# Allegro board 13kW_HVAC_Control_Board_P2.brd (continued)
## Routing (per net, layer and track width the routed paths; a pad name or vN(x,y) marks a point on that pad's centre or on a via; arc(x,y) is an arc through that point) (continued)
NETD4_1: length 16.3
  BOTTOM w0.508: U9.6 69.72,33.66 71.64,31.73 71.64,27.06 71.13,26.54 69.9,26.54 69.28,25.93 69.28,24.91 D4.1 D6.2 69.43,22.57 68.56,21.7 T1.1
NETDACA_1: length 2.7
  TOP w0.305: R140.2 24.92,14.1 DACA.1
NETDACB_1: length 2.8
  TOP w0.305: DACB.1 25.27,15.62 R142.2
NETIC1_1: length 7.4
  TOP w0.254: IC1.1 58.45,34.31 57.93,33.78 57.93,30.34 R33.2
NETJ4_5: length 7.2
  BOTTOM w0.254: R20.1 51.44,9.6 53.98,7.06 53.98,5.31 J4.5
NETJ4_9: length 9
  BOTTOM w0.254: J4.11 J4.9 48.9,5.31 48.9,7.62 47.76,8.75 R24.1
NETJ4_13: length 6.1
  BOTTOM w0.254: J4.13 46.35,5.31 R25.2
NETJ4_14: length 3.1
  BOTTOM w0.254: R23.2 J4.14
NETQ1_1: length 2.9
  BOTTOM w0.305: Q1.1 2.86,10.35 R18.2 R15.1
NETQ2_1: length 1.4
  TOP w0.508: R34.2 68.58,16.13 Q2.1
NETR7_1: length 6.5
  TOP w0.203: v2(50.33,20.32) 48.64,20.32 47.51,21.46 U1.64
  BOTTOM w0.254: R7.1 v2(50.33,20.32)
NETR8_1: length 4.9
  TOP w0.203: v2(47.62,14.28) 47.89,14.55 47.89,17.08 47.66,17.31 47.46,17.31 47.32,17.45 U1.56
  BOTTOM w0.254: R8.1 v2(47.62,14.28)
NETR12_2: length 3.8
  TOP w0.381: U2.19 13.64,7.95 13.72,7.87 R12.2 R13.2
NETR14_2: length 3.2
  TOP w0.381: R14.2 4.2,5.71 5.13,6.64 U2.8
NETR36_1: length 17.8
  TOP w0.203: U1.54 45.65,16.45 45.49,16.3 45.49,14.17 45.28,13.96 45.28,12.37 v1(44.65,11.74)
  GND02 w0.203: v1(42.71,5.66) 42.39,5.98 42.39,10.85 43.28,11.74 v1(44.65,11.74)
  BOTTOM w0.203: R36.1 39.73,4.55 40.84,5.66 v1(42.71,5.66)
NETR37_1: length 18.3
  TOP w0.203: U1.55 47.35,16.96 47.54,16.77 47.54,14.84 47.05,14.35 46.61,14.35 45.65,13.39 45.65,12 45.45,11.79 v1(45.45,11.71)
  GND02 w0.203: v1(45.45,11.71) 44.89,11.15 43.27,11.15 42.72,10.6 42.72,6.42 43.28,5.86 43.28,5.21 v1(42.68,4.61)
  BOTTOM w0.203: R37.1 v1(42.68,4.61)
NETR39_1: length 2.2
  TOP w0.508: R161.1 22.86,34.08 R39.1
NETR47_1: length 2.3
  TOP w0.508: R48.2 R47.1
NETR54_1: length 5
  TOP w0.508: U4.2 19.68,18.8 19.56,18.92 18.67,18.92 18.41,18.67 U4.1 R54.1
NETR69_1: length 2.3
  TOP w0.508: R69.1 R70.2
NETR71_1: length 2.3
  TOP w0.508: R72.2 R71.1
NETR75_2: length 2.6
  TOP w0.508: R75.2 69.66,28.42 70.2,28.89 v2(70.23,29.21)
  BOTTOM w0.508: U9.8 v2(70.23,29.21)
NETR78_1: length 2.3
  TOP w0.508: R79.2 R78.1
NETR83_1: length 2.3
  TOP w0.508: R83.1 R84.2
NETR89_1: length 2.3
  TOP w0.508: R90.2 R89.1
NETR91_1: length 2.3
  TOP w0.508: R92.2 R91.1
NETR94_1: length 12
  TOP w0.254: R94.1 57.78,21.08 57.53,20.83 57.53,13.97 58.8,12.7 59.56,12.7 60.2,12.06 U10.8
NETR95_2: length 10.1
  TOP w0.254: R95.2 56.77,21.34 57.02,21.08 57.02,13.84 56.52,13.34 U10.6
NETR97_1: length 9.4
  TOP w0.254: U10.10 60.2,14.61 59.56,15.24 58.93,15.24 58.04,16.13 58.04,20.32 58.42,20.7 58.42,21.47 R97.1
NETR100_2: length 8.6
  TOP w0.254: R100.2 54.74,21.34 54.48,21.08 53.94,21.08 52.96,20.1 52.96,18.8 53.42,18.34 53.42,16.56 54.1,15.88 U10.4
NETR102_1: length 7.2
  TOP w0.254: R102.1 59.82,20.83 59.31,20.32 58.8,20.32 58.55,20.07 58.55,18.16 58.93,17.78 59.56,17.78 60.2,17.14 U10.12
NETR104_2: length 6.5
  TOP w0.254: R104.2 55.75,21.08 55.24,20.57 53.98,20.57 53.47,20.07 53.47,19.05 54.1,18.41 U10.2
NETR114_1: length 3.9
  TOP w0.254: U1.35 37.23,12.51 35.56,10.84 R114.1
NETR116_1: length 3.5
  TOP w0.254: R116.1 28.57,22.23 29.06,22.71 30.04,22.71 30.3,22.46 U1.10
NETR117_1: length 3.9
  TOP w0.254: U1.6 30.03,24.46 29.21,25.27 29.21,25.9 R117.1
NETR118_1: length 3.5
  TOP w0.254: U1.38 38.73,10.66 R118.1
NETR120_1: length 2.9
  TOP w0.254: U1.8 30.27,23.46 29.09,24.63 R120.1
NETR122_1: length 3.3
  TOP w0.254: U1.39 39.24,10.16 R122.1
NETR124_1: length 2.6
  TOP w0.254: R124.1 29.27,18.28 29.59,17.96 U1.19
NETR127_1: length 6.9
  TOP w0.254: R127.1 30.49,11.3 33.27,11.3 34.23,12.26 U1.29
NETR129_1: length 11.3
  TOP w0.254: v1(27.39,16.38) 28.88,16.38 29.45,16.96 U1.21 ; v1(27.25,13.14) 27.25,13.11 26.97,12.83 24.26,12.83 23.89,12.46 R129.1
  GND02 w0.254: v1(27.25,13.14) 27.25,16.24 v1(27.39,16.38)
NETR140_1: length 3.9
  TOP w0.254: R140.1 29.07,14.1 29.34,14.36 29.34,15.38 29.92,15.96 U1.23
NETR142_1: length 2.9
  TOP w0.254: R142.1 28.83,15.62 29.66,16.45 U1.22
NETR155_2: length 5
  TOP w0.254: U1.31 35.23,11.87 34.67,11.3 34.04,11.3 32.76,10.02 R155.2
NETR158_2: length 9.5
  TOP w0.254: R158.2 26.46,10.02 26.97,10.54 27.01,10.54 27.23,10.76 27.23,10.8 27.74,11.3 29.21,11.3 29.72,11.81 33.15,11.81 33.74,12.4 U1.28
NETT1_2: length 2.4
  BOTTOM w0.508: T1.2 T2.1
NETT1_3: length 2.4
  BOTTOM w0.508: T2.4 T1.3
NETU6_6: length 2.7
  BOTTOM w0.508: U6.7 15.88,23.24 16.13,22.99 16.89,22.99 17.14,23.24 17.14,23.87
P_-2.7V: length 23.3
  TOP w0.508: U11.4 42.55,43.18 v2(41.91,42.55)
  GND03 w0.508: v2(41.91,42.55) 41.15,43.31 36.45,43.31 34.82,41.68 26.67,41.68 J1.20
  BOTTOM w0.508: C111.1 C112.2 42.55,43.19 42.55,43.18 v2(41.91,42.55) 42.55,41.91 U12.4
PWM-1A: length 28.1
  TOP w0.254: R94.2 57.78,23.39 57.04,24.13 57.04,26.7 56.44,27.3 56.44,38.56 55.24,39.75 55.24,41.02 55.88,41.66 57.02,41.66 57.78,42.42 57.78,43.69 57.28,44.2 55.22,44.2 J2.2
PWM-1AA: length 36.8
  TOP w0.254: U1.79 43.24,29.79 v2(42.55,30.48) R1.2
  BOTTOM w0.254: v2(42.55,30.48) 44.32,28.7 47.06,28.7 47.94,27.81 53.21,27.81 54.61,26.42 54.61,23.16 52.78,21.33 52.78,16.44 55.24,13.97 57.28,13.97 59.18,12.06 R96.1
PWM-1B: length 26.5
  TOP w0.254: R95.1 56.77,23.41 56.29,23.89 56.29,26.44 55.23,27.5 55.23,36.56 55.88,37.21 55.88,38.35 55.5,38.73 53.21,38.73 52.83,39.12 52.83,41.53 53.09,41.78 54.74,41.78 55.9,42.95 J2.4
PWM-1BB: length 28.6
  TOP w0.254: U1.78 43.73,30.4 v2(43.81,30.48) R2.2
  BOTTOM w0.254: v2(43.81,30.48) 43.81,29.97 44.58,29.21 47.62,29.21 48.64,28.19 53.37,28.19 54.99,26.57 54.99,22.85 53.34,21.2 53.34,16.76 54.23,15.88 R98.1
PWM-2A: length 21.8
  TOP w0.254: R97.2 58.8,23.27 57.71,24.36 57.71,26.85 56.9,27.66 56.9,37.89 57.78,38.78 57.78,41.68 J2.6
PWM-2AA: length 30.7
  TOP w0.254: R3.2 v2(45.09,30.48) 44.24,29.63 U1.77
  BOTTOM w0.254: v2(45.09,30.48) 45.72,31.11 47.88,31.11 49.66,29.34 53.84,29.34 56.13,27.05 56.13,22.61 57.91,20.83 57.91,18.03 58.55,17.4 58.55,15.62 58.93,15.24 59.19,15.24 R99.1
PWM-2B: length 29.8
  TOP w0.254: R100.1 54.74,23.24 55.34,23.85 55.34,26.26 54.41,27.19 54.41,37.66 v2(53.98,38.1)
  BOTTOM w0.254: J2.8 62.87,41.68 62.87,39.88 62.23,39.24 61.34,39.24 60.58,38.48 57.4,38.48 56.39,37.47 54.61,37.47 v2(53.98,38.1)
PWM-2BB: length 25
  TOP w0.254: U1.76 44.73,29.34 44.99,29.59 45.47,29.59 v2(46.35,30.48) R4.2
  BOTTOM w0.254: v2(46.35,30.48) 47.88,30.48 49.4,28.96 53.69,28.96 55.75,26.89 55.75,22.35 57.02,21.08 57.02,18.92 56.52,18.41 R101.1
PWM-3A: length 19.3
  TOP w0.254: J2.5 59.05,38.78 57.33,37.05 57.33,28.02 58.36,26.99 58.36,24.57 59.82,23.11 R102.2
PWM-3AA: length 25.3
  TOP w0.254: v2(50.16,30.48) 48.4,28.71 R5.2 47.5,27.3 47.15,26.95 U1.75
  BOTTOM w0.254: v2(50.16,30.48) 50.8,29.84 53.88,29.84 56.52,27.21 56.52,22.86 58.42,20.95 58.42,18.29 58.93,17.78 59.19,17.78 R103.1
PWM-3B: length 23.1
  TOP w0.254: R104.1 55.75,26.39 54.79,27.35 54.79,37.65 v2(55.24,38.1)
  BOTTOM w0.254: v2(55.24,38.1) 56.12,38.1 57.14,39.12 60.3,39.12 J2.7
PWM-3BB: length 27.9
  TOP w0.254: R6.2 v2(41.27,31.11) 40.51,30.35 38.51,30.35 38.24,30.08 U1.89
  BOTTOM w0.254: R105.2 54.75,21.45 55.37,22.08 55.37,26.73 53.53,28.57 49.02,28.57 47.88,29.72 44.96,29.72 44.45,30.23 44.45,30.73 44.07,31.11 v2(41.27,31.11)
R_12V: length 18.4
  TOP w0.508: J3.1 70.87,18.29 70.87,19.73 71.88,20.75 71.88,33.53 71.1,34.31 IC1.4
R_GND: length 10.2
  TOP w0.508: R35.1 66.67,17.41 ; 66.67,17.41 66.61,17.35 66.61,16.06 Q2.2 66.61,15.04 66.61,15.03 66.61,13.06 67.12,12.55 70.21,12.55 J3.3 ; 66.67,17.41 67.31,17.41 C35.2
REF1.65: length 22.4
  TOP w0.508: C94.1 41.27,43.18 v2(40.64,42.55) 40.01,43.18 R107.2 ; C98.1 40.01,39.37 v2(40.64,40.01) 41.27,39.37 R139.2
  GND03 w0.508: v1(45.23,39.37) 41.27,39.37 v2(40.64,40.01) v2(40.64,42.55)
  BOTTOM w0.508: R147.2 40.01,41.91 v2(40.64,42.55) 41.27,41.91 C103.1 ; U12.6 45.74,40.64 45.23,40.13 v1(45.23,39.37) U12.7
RELAY: length 39.7
  TOP w0.254: U1.50 44.73,12.55 44.05,11.87 44.05,11.32 44.22,11.15 45.86,11.15 46.21,10.79 46.7,10.79 46.7,10.79 61.15,10.79 63.2,12.84 63.2,19.72 62.55,20.37 61.36,20.37 60.73,21 60.73,23.05 59.73,24.04 59.73,27.54 R33.1
RLY: length 3.9
  TOP w0.508: J3.2 68.97,13.86 Q2.3
SCIA_RX: length 2.1
  BOTTOM w0.254: J6.2 41.35,3.6 R37.2
SCIA_TX: length 2.6
  BOTTOM w0.254: R36.2 38.81,4.02 J6.1
SCL: length 7.5
  TOP w0.203: v2(50.16,14.61) U3.6 50.16,16.76 48.63,18.3 47.99,18.3 47.34,18.96 U1.59
  BOTTOM w0.254: R31.1 v2(50.16,14.61)
SDA: length 6.5
  TOP w0.203: v2(48.9,14.61) 48.9,17.44 48.36,17.97 47.81,17.97 47.33,18.45 U1.58
  BOTTOM w0.254: R30.1 v2(48.9,14.61)
TCK_P: length 13.7
  TOP w0.203: U1.60 47.35,19.45 48.17,18.63 48.87,18.63 49.35,18.15 49.8,18.15 v2(50.16,17.78)
  BOTTOM w0.203: R24.2 R22.1 48.76,11.44 48.26,11.94 48.26,15.88 v2(50.16,17.78)
TDI_P: length 24.4
  TOP w0.203: U1.63 47.47,20.95 48.74,19.68 50.77,19.68 51.44,19.02 v2(51.44,17.76)
  BOTTOM w0.203: v2(51.44,17.76) 51.44,15.37 52.07,14.73 52.07,10.22 52.63,9.66 R19.1 54.17,8.2 55.81,8.2 56.52,7.49 56.52,5.31 J4.3
TDO_P: length 21.3
  TOP w0.203: v2(50.67,18.51) 50.59,18.59 49.52,18.59 49.11,19 48.27,19 47.31,19.96 U1.61
  BOTTOM w0.203: R21.1 49.78,9.66 49.53,9.91 49.53,16 50.67,17.14 v2(50.67,18.51)
  BOTTOM w0.254: J4.7 51.44,5.31 51.44,7.75 50.16,9.02 R21.1
TEMP: length 25.1
  TOP w0.254: v2(21.59,22.23) 20.95,21.59 U4.3
  BOTTOM w0.254: v2(21.59,22.23) R56.2 20.32,23 C46.2 19.93,22.99 19.68,23.24 19.68,33.4 19.05,34.04 19.05,39.14 J1.13
TEMP1: length 19.5
  TOP w0.254: R117.2 26.48,26.67 v2(26.23,26.42) 25.1,26.42 23.8,25.12 23.19,25.12 22.94,24.87 22.94,17.04 20.63,14.74 C47.1 R54.2
  BOTTOM w0.254: v2(26.23,26.42) 26.21,26.42 26.2,26.43 D8.3
TMS_P: length 28.2
  TOP w0.203: U1.62 47.39,20.46 48.52,19.33 49.43,19.33 v2(49.71,19.05)
  BOTTOM w0.203: v2(49.71,19.05) 51.43,19.05 52.2,18.28 52.2,16 54.58,13.61 54.58,10.2 54.35,9.96 54.27,9.96 R17.1 53.98,9.6 54.68,8.89 57.78,8.89 59.05,7.62 59.05,5.31 J4.1
  BOTTOM w0.254: R10.1 v2(49.71,19.05)
TRST_P: length 4.9
  BOTTOM w0.381: R16.2 59.05,9.66 C19.2 59.05,8.64 60.33,7.37 J4.2
U_SAMPLE: length 8.9
  TOP w0.381: J1.4 4.51,42.95 3.97,42.41 3.97,42.12 4.44,41.65 5.98,41.65 6.35,41.29 6.35,37.6 R69.2
V_SAMPLE: length 11.4
  TOP w0.381: v1(9.09,38.32) 9.09,38.03 R78.2
  GND02 w0.381: J1.6 8.1,42.95 9.4,41.66 11.05,41.66 11.43,41.27 11.43,38.7 11.05,38.32 v1(9.09,38.32)
VA+5V: length 6.8
  TOP w0.508: R86.2 v2(15.88,13.97) ; R137.2 50.16,39.37 ; R66.2 2.54,26.67 v2(1.91,27.3)
  BOTTOM w0.508: v2(16.51,19.68) 17.14,20.32 R60.2 ; v2(1.91,19.68) 2.54,19.05 R150.2 ; R145.2 v2(45.72,34.92) ; R148.2 v2(21.59,19.68)
  vias: v2(1.91,9.53) v2(1.91,8.26) v2(2.54,4.45) v2(3.81,9.53) v2(3.81,4.45) v2(5.08,4.45) v2(50.8,38.73) v2(50.8,38.1)
VD+5V: length 16.2
  BOTTOM w0.762: v2(50.8,34.29) v2(50.8,33.66) 50.8,32.77 52.96,30.61 54.48,30.61 57.53,27.56 57.53,24.38 58.42,23.5 R109.1
VU: length 44.2
  TOP w0.254: v2(23.74,6.41) 23.69,6.41 22.89,7.21 R128.2 22.05,8.69 21.16,9.58 21.16,12.33 v1(22.68,13.84)
  BOTTOM w0.254: v2(23.74,6.41) 21.15,3.82 15.36,3.82 11.3,7.87 11.3,11.81 10.67,12.45 10.67,14.79 6.41,19.05 C56.1 5.69,19.32 5.69,19.59 R67.1 ; v1(22.68,13.84) 24.34,13.84 25.11,14.61 D9.3
VV: length 45.7
  TOP w0.254: 27.94,6.49 v2(27.94,5.72) 27.76,5.53 23.93,5.53 23.54,5.93 23.54,5.93 23.25,6.21 23.25,6.21 v2(21.97,7.49) 20.78,8.68 20.78,12.91 v1(21.69,13.82)
  BOTTOM w0.254: v2(21.97,7.49) 19.87,5.4 16.07,5.4 12.67,8.79 12.67,12.83 12.22,13.28 12.22,15.62 10.08,17.75 10.08,19.84 10.7,20.45 C63.1 11.43,20.46 R76.1 ; R125.2 23.12,15.25 v1(21.69,13.82) ; D10.3 v2(27.94,5.72)
VW: length 43
  TOP w0.254: v2(19.68,6.35) 19.97,6.35 22.65,3.67 34.85,3.67 36.79,5.61 v2(38.03,5.61) 38.03,6.44 R123.2
  BOTTOM w0.254: R87.1 11.43,17.92 C69.1 11.43,17.14 12.7,15.88 12.7,13.46 13.08,13.08 13.08,9.14 16.37,5.85 19.19,5.85 v2(19.68,6.35) ; v2(38.03,5.61) 39.73,5.61 D11.3
W_SAMPLE: length 11.1
  TOP w0.381: R89.2 14.34,37.86 v1(14.34,38.31)
  GND02 w0.381: v1(14.34,38.31) 16.13,38.31 16.51,38.69 16.51,41.15 16,41.66 14.35,41.66 13.06,42.95 J1.10
WP: length 10.9
  TOP w0.203: U1.57 47.32,17.96 47.64,17.64 47.8,17.64 48.22,17.22 48.22,14.39 48.51,14.1 50.93,14.1 v2(51.44,14.61) 51.44,16.25
  BOTTOM w0.254: R32.1 v2(51.44,14.61)
XRS: length 68
  TOP w0.254: U1.2 30.06,26.46 29.84,26.67 29.84,27.43 31.11,28.7 v2(31.11,29.84) 29.88,29.84 27.57,27.54 24.44,27.54 v2(24.14,27.24) ; v2(17.78,6.99) 17.65,6.86 R13.1 ; v2(1.91,3.17) 1.91,4.94 R14.1
  GND03 w0.254: v2(1.91,3.17) 2.54,2.54 13.34,2.54 v2(17.78,6.99)
  BOTTOM w0.254: v2(31.11,29.84) 31.75,29.84 32.38,30.48 C15.1 33.15,29.21 R9.1 ; v2(17.78,6.99) 16.64,6.99 14.1,9.53 14.1,12.4 14.45,12.75 16.71,12.75 18.39,14.44 20.38,14.44 23.5,17.55 23.5,24 24.14,24.65 v2(24.14,27.24)

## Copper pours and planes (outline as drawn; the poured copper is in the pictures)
AGND on TOP (solid shape): 37.72,22.1 37.72,15.49 37.47,15.24 36.83,15.24 36.58,14.99 36.58,14.61 36.2,14.22 32.26,14.22 32.13,14.35 32.13,22.35 32.26,22.48 37.34,22.48
AGND on TOP (solid shape): 32.13,38.35 33.53,38.35 35.31,36.58 35.31,36.07 34.49,36.07 34.49,35.35 34.05,35.35 33.5,35.9 33.5,36.17 33.43,36.45 33.21,36.64 33.15,36.7 30.73,36.7 30.61,36.58 30.32,36.58 26.26,32.51 25.91,32.51 25.84,32.58 25.82,32.63 25.78,32.68 25.78,39.24 25.91,39.37 31.11,39.37
AGND on TOP (solid shape): outline of 96 points within 5.87,17.07 9.91,27.69
AGND on BOTTOM (solid shape): 32.13,22.48 37.34,22.48 37.72,22.1 37.72,15.49 37.47,15.24 36.83,15.24 36.58,14.99 36.58,13.84 36.45,13.72 32.26,13.72 31.37,14.61 31.37,22.48 31.5,22.61 32,22.61
AGND on BOTTOM (solid shape): 26.67,33.62 26.67,32.87 25.72,31.92 25.03,31.92 21.97,28.86 21.97,24.57 21.08,24.57 21.08,23.75 20.83,23.75 20.83,24.57 20.07,24.57 20.07,33.56 19.43,34.19 19.43,38.99 19.68,39.24 21.05,39.24
AGND on TOP: 1.27,0.51 0.73,0.73 0.51,1.27 0.51,45.72 0.73,46.26 1.27,46.48 51.56,46.48 51.69,46.35 51.69,40.39 51.56,40.26 50.53,40.26 50.4,40.39 50.4,41.51 50.79,41.9 50.79,43.75 50.68,43.87 49.7,43.87 48.91,43.08 47.31,43.08 47.07,43.32 47.07,44.37 45.98,45.46 39.82,45.46 38.93,44.58 37.59,44.58 37.59,43.76 35.87,43.76 33.93,45.7 29.34,45.7 28.09,44.45 20.45,44.45 20.45,44.39 1.66,44.39 1.43,44.16 1.43,39.42 3.25,37.59 3.25,29.93 1.25,27.92 1.25,26.54 2.13,25.65 2.13,23.39 2.17,23.35 2.86,23.35 2.9,23.3 2.9,17.24 3.11,17.04 5.68,17.04 5.92,17.28 8.44,17.28 9.13,16.59 11.45,16.59 12.9,15.13 15.03,15.13 15.13,15.03 15.13,13.86 14.95,13.68 12.63,13.68 11.9,14.42 8.47,14.42 8.3,14.25 8.3,12.9 8.58,12.63 15.67,12.63 16.18,12.12 16.18,11.01 16.11,10.94 11.71,10.94 11.33,10.56 11.33,4.67 11.67,4.33 13.37,4.33 13.62,4.08 13.62,3.53 13.84,3.31 19.77,3.31 21.57,1.5 35.73,1.5 36.04,1.19 36.04,0.51 ; 2 cut-outs
AGND on BOTTOM: outline of 112 points within 0.51,0.51 51.82,46.48
AGND on GND02: 1.27,0.51 0.73,0.73 0.51,1.27 0.51,45.72 0.73,46.26 1.27,46.48 51.69,46.48 51.69,36.99 51.28,36.58 50.01,36.58 49.15,35.72 49.15,35.08 48.74,34.67 34.13,34.67 33.27,33.81 33.27,28.73 31.37,26.83 31.37,23.34 32.23,22.48 37.31,22.48 37.72,22.07 37.72,15.08 41.12,11.68 41.75,11.68 42.16,11.27 42.16,0.51 ; 1 cut-out
AGND on GND03: 1.27,0.51 0.73,0.73 0.51,1.27 0.51,45.72 0.73,46.26 1.27,46.48 18.91,46.48 18.86,46.43 18.86,42.47 18.92,42.4 18.92,36.97 10.72,28.77 1.83,28.77 1.08,28.02 1.08,4.95 2.1,3.93 6.1,3.93 15.32,13.14 21.67,13.14 22.42,13.89 22.42,30.4 25.48,33.46 33.27,33.46 33.27,28.73 31.37,26.83 31.37,23.34 32.23,22.48 37.31,22.48 37.72,22.07 37.72,15.08 41.12,11.68 41.75,11.68 42.16,11.27 42.16,0.51
DGND on TOP (solid shape): 36.83,27.43 36.83,27.05 37.08,26.8 44.32,26.8 44.58,26.54 44.58,22.86 44.7,22.73 45.21,22.73 45.34,22.61 45.34,16.86 45.21,16.73 45.21,14.51 45.08,14.38 44.85,14.38 44.73,14.5 44.73,14.85 44.72,14.85 44.72,15.27 44.49,15.49 38.99,15.49 38.48,16 38.48,22.48 37.72,23.24 32.64,23.24 32.26,23.62 32.26,24.89 32.38,25.02 32.89,25.02 33.02,25.15 33.02,27.18 33.53,27.69 36.58,27.69
DGND on TOP (solid shape): 62.61,38.99 62.61,24.38 62.36,24.13 60.58,24.13 60.2,24.51 60.2,24.77 61.11,24.77 61.12,24.7 61.13,24.64 61.15,24.58 61.17,24.53 61.21,24.48 61.25,24.43 61.29,24.39 61.34,24.35 61.4,24.32 61.46,24.3 61.52,24.29 61.58,24.28 61.64,24.28 61.7,24.29 61.76,24.31 61.82,24.34 61.87,24.37 61.92,24.41 61.96,24.45 62,24.5 62.03,24.56 62.05,24.61 62.07,24.67 62.08,24.73 62.08,24.8 62.07,24.86 62.05,24.92 62.03,24.97 62,25.03 61.96,25.08 61.92,25.12 61.87,25.16 61.82,25.19 61.76,25.22 61.7,25.24 61.64,25.25 61.58,25.25 61.52,25.24 61.46,25.23 61.4,25.21 61.34,25.18 61.29,25.14 61.25,25.1 61.21,25.05 61.17,25 61.15,24.95 61.13,24.89 61.12,24.83 61.11,24.77 60.2,24.77 60.2,25.02 60.72,25.55 60.72,30.15 60.19,30.68 58.75,30.68 58.43,31.01 58.43,32.83 58.78,33.19 60.58,33.19 61.14,33.74 61.14,35.14 60.59,35.69 58.76,35.69 58.59,35.87 58.59,37.55 60.24,39.2 61.27,39.2 61.31,39.24 62.36,39.24
DGND on TOP (solid shape): outline of 976 points within 43.4,0.51 62.61,11.17
DGND on BOTTOM (solid shape): 53.21,26.54 53.21,23.62 52.7,23.11 48.89,23.11 48.64,23.37 48.64,23.88 49.02,24.26 49.02,26.54 49.15,26.67 53.09,26.67
DGND on BOTTOM (solid shape): 62.61,11.3 62.61,0.51 43.81,0.51 43.38,0.94 43.38,2.92 61.21,2.92 61.47,3.17 61.47,8.38 60.58,9.27 60.58,10.92 61.09,11.43 62.48,11.43
DGND on BOTTOM (solid shape): 46.83,33.74 46.83,32.66 46.8,32.64 40.99,32.64 40.77,32.64 39.24,31.11 36.07,31.11 35.18,30.23 34.04,30.23 33.91,30.35 33.91,31.11 34.16,31.37 34.16,32.13 35.11,33.09 39.04,33.09 39.86,33.91 46.66,33.91
DGND on BOTTOM (solid shape): 36.58,27.18 36.96,26.8 39.37,26.8 39.5,26.92 39.5,28.07 41.63,28.07 41.78,27.91 41.78,26.42 41.91,26.29 45.82,26.29 45.97,26.13 45.97,25.65 45.85,25.53 44.83,25.53 44.58,25.27 44.58,22.86 44.7,22.73 45.72,22.73 45.97,22.48 45.97,21.97 45.34,21.34 45.34,21.24 45.34,15.78 45.18,15.62 43.15,15.62 43.02,15.49 42.16,15.49 41.66,14.99 41.66,13.72 42.04,13.34 42.16,13.34 42.42,13.08 42.42,12.57 42.29,12.45 41.4,12.45 39.22,14.63 39.08,14.95 38.76,15.09 38.48,15.37 38.48,22.35 37.59,23.24 32.64,23.24 32.26,23.62 32.26,24.89 32.36,24.99 32.54,24.99 32.58,24.95 32.58,24.89 33.73,24.89 33.73,24.96 33.78,25.02 33.78,25.88 33.91,26 33.91,26.77 35.21,28.07 36.58,28.07
DGND on TOP: 51.56,26.67 51.18,27.05 51.18,29.69 53,31.5 53,33.81 52.45,34.35 52.45,37.34 52.58,37.47 53.98,37.47 54.03,37.41 54.03,27.82 52.88,26.67
DGND on TOP: 52.45,44.7 52.45,46.48 62.61,46.48 62.61,44.96 62.36,44.7
DGND on BOTTOM: 56.77,29.34 54.86,31.24 53.59,31.24 53.21,31.62 53.21,31.88 53.34,32 55.25,32 55.5,31.75 56.64,31.75 56.9,31.5 56.9,30.61 57.15,30.35 61.47,30.35 61.59,30.48 61.66,30.48 61.66,30.54 61.72,30.61 61.72,35.05 61.34,35.43 58.42,35.43 58.17,35.69 54.61,35.69 53.85,34.92 52.2,34.92 51.82,35.31 51.82,36.07 52.45,36.7 52.45,46.48 62.61,46.48 62.61,44.32 62.23,43.94 61.81,43.94 61.59,43.97 61.38,43.94 60.96,43.94 60.58,43.56 60.58,42.47 59.94,41.84 59.94,41.78 59.56,41.4 59.27,41.4 59.05,41.43 58.84,41.4 58.29,41.4 58.04,41.15 58.04,40.01 57.78,39.75 56.9,39.75 56.13,38.99 53.72,38.99 53.47,38.73 53.47,37.59 54.1,36.96 56.52,36.96 57.28,37.72 59.44,37.72 59.56,37.72 59.94,38.1 62.48,38.1 62.61,37.97 62.61,29.46 62.48,29.34 58.9,29.34 58.9,29.34
DGND on GND02: 42.93,0.51 42.93,11.59 42.07,12.45 41.43,12.45 38.48,15.4 38.48,22.38 37.62,23.24 32.54,23.24 32.13,23.65 32.13,26.51 34.04,28.42 34.04,33.5 34.45,33.91 49.05,33.91 49.91,34.77 49.91,35.4 50.32,35.81 51.59,35.81 52.45,36.67 52.45,46.48 62.61,46.48 62.61,0.51
DGND on GND03: 42.93,0.51 42.93,7.37 45.83,7.37 46.61,8.15 46.61,27.41 45.83,28.19 33.81,28.19 34.04,28.42 34.04,33.5 34.45,33.91 49.05,33.91 49.91,34.77 49.91,35.4 50.32,35.81 51.59,35.81 52.45,36.67 52.45,46.48 62.61,46.48 62.61,0.51
A_1.2V on TOP (solid shape): 42.16,10.79 42.16,3.7 41.24,2.78 37.75,2.78 36.37,1.4 20.57,1.4 20.32,1.65 20.32,3.17 20.07,3.43 14.1,3.43 13.97,3.56 13.97,4.32 13.72,4.57 11.94,4.57 11.81,4.7 11.81,5.33 11.94,5.46 20.09,5.46 22.37,3.17 35.38,3.17 37.11,4.91 39.35,4.91 40.01,5.56 40.01,10.67 40.39,11.05 41.91,11.05
A_3.3V on TOP (solid shape): 18.73,10.79 18.73,9.36 18.51,9.14 14.22,9.14 13.59,9.78 11.94,9.78 11.81,9.91 11.81,10.54 11.94,10.67 13.84,10.67 13.97,10.54 16.51,10.54 16.89,10.92 18.59,10.92
A_3.3V on BOTTOM: outline of 110 points within 14.99,8.13 42.16,41.66
CAN+5V on TOP: 66.58,29.21 66.58,36.29 65.66,37.21 65.66,41.4 65.91,41.66 69.09,41.66 69.34,41.4 69.34,38.99 67.97,37.62 67.97,30.2 68.07,30.1 69.34,30.1 69.6,29.84 69.6,29.21 69.47,29.08 66.71,29.08
CAN_GND on TOP: 65.66,42.42 65.91,42.16 68.2,42.16 68.33,42.04 69.22,42.04 69.85,41.4 69.85,38.48 68.07,36.7 68.07,35.81 68.33,35.56 70.74,35.56 71.75,34.54 71.75,11.56 71.12,10.92 66.55,10.92 65.15,9.53 65.15,-0.51 67.18,-2.54 72.01,-2.54 76.45,1.91 76.45,45.59 72.26,49.78 66.17,49.78 65.66,49.28
CAN_GND on BOTTOM: 65.66,42.42 65.91,42.16 68.2,42.16 68.33,42.04 69.22,42.04 69.85,41.4 69.85,38.48 68.07,36.7 68.07,35.81 68.33,35.56 70.74,35.56 71.75,34.54 71.75,24.26 70.68,23.18 70.68,22.42 70.23,21.97 69.98,21.97 69.72,21.72 69.72,20.95 71.75,18.92 71.75,11.56 71.12,10.92 71.12,3.43 70.23,2.54 65.66,2.54 65.15,2.03 65.15,-0.51 67.18,-2.54 72.01,-2.54 76.45,1.91 76.45,45.59 72.26,49.78 66.17,49.78 65.66,49.28
CAN_GND on GND02, GND03: 65.66,42.42 65.91,42.16 67.82,42.16 67.82,37.59 67.31,37.08 67.31,24 65.91,22.61 65.91,20.45 67.18,19.18 67.18,5.08 67.69,4.57 67.69,0.51 70.74,-2.54 72.01,-2.54 76.45,1.91 76.45,45.59 72.26,49.78 66.17,49.78 65.66,49.28
D_1.2V on TOP (solid shape): 44.23,10.6 45.41,10.6 45.47,10.54 45.47,8.82 45.25,8.6 43.1,8.6 42.93,8.77 42.93,10.79 43.05,10.92 43.91,10.92
D_1.2V on GND03: 42.93,7.87 42.93,11.59 42.07,12.45 41.43,12.45 38.75,15.13 38.75,22.11 37.62,23.24 37.59,23.24 37.34,23.5 32.29,23.5 32.13,23.65 32.13,26.51 33.3,27.69 45.61,27.69 46.1,27.2 46.1,8.36 45.61,7.87
D_3.3V on TOP (solid shape): 53.72,14.86 53.72,12.06 54.23,11.56 54.23,11.23 54.17,11.17 52.17,11.17 51.88,11.46 46.34,11.46 46.1,11.7 46.1,12.06 52.22,12.06 52.23,12 52.24,11.94 52.26,11.88 52.28,11.83 52.32,11.78 52.36,11.73 52.4,11.69 52.45,11.65 52.51,11.62 52.57,11.6 52.63,11.59 52.69,11.58 52.75,11.58 52.81,11.59 52.87,11.61 52.93,11.64 52.98,11.67 53.03,11.71 53.07,11.75 53.11,11.8 53.14,11.86 53.16,11.91 53.18,11.97 53.19,12.03 53.19,12.1 53.18,12.16 53.16,12.22 53.14,12.27 53.11,12.33 53.07,12.38 53.03,12.42 52.98,12.46 52.93,12.49 52.87,12.52 52.81,12.54 52.75,12.55 52.69,12.55 52.63,12.54 52.57,12.53 52.51,12.51 52.45,12.48 52.4,12.44 52.36,12.4 52.32,12.35 52.28,12.3 52.26,12.25 52.24,12.19 52.23,12.13 52.22,12.06 46.1,12.06 46.1,13.25 46.32,13.46 51.69,13.46 52.07,13.84 52.07,14.86 52.2,14.99 53.59,14.99
D_3.3V on BOTTOM (solid shape): outline of 244 points within 32.13,10.16 48.64,30.73
NETC52_1 on BOTTOM (solid shape): 50.55,43.56 50.55,41.91 50.16,41.53 48.26,41.53 48.26,43.56 48.39,43.69 50.42,43.69
NETC60_2 on BOTTOM (solid shape): 62.61,28.83 62.61,26.42 62.48,26.29 59.05,26.29 58.93,26.42 58.93,28.83 59.05,28.96 62.48,28.96
NETC81_1 on TOP (solid shape): 26.64,22.1 26.64,20.9 26.75,20.8 28.8,20.8 28.88,20.73 28.88,20.09 28.8,20.02 23.5,20.02 23.39,20.12 23.39,22.4 23.47,22.48 26.26,22.48
NETC86_1 on TOP (solid shape): 26.59,19.35 26.59,17.83 26.77,17.65 28.8,17.65 28.91,17.55 28.91,16.99 28.88,16.97 26.72,16.97 26.44,17.25 23.34,17.25 23.34,19.43 23.5,19.58 26.37,19.58
NETC88_1 on TOP (solid shape): 26.49,24.56 26.49,24.23 26.75,23.98 28.8,23.98 28.88,23.9 28.88,23.34 28.8,23.27 28.32,23.27 27.91,22.86 23.5,22.86 23.34,23.01 23.34,24.56 23.42,24.64 26.42,24.64
NETDACA_1 on TOP (solid shape): 26.64,14.63 27.56,14.63 27.79,14.4 27.79,13.79 27.74,13.74 26.82,13.74 26.8,13.72 26.77,13.72 26.26,13.21 23.29,13.21 23.25,13.25 23.25,14.74 26.53,14.74
NETDACB_1 on TOP (solid shape): 26.87,15.88 27.74,15.88 27.81,15.8 27.81,15.27 27.74,15.19 26.7,15.19 26.59,15.29 23.32,15.29 23.25,15.35 23.25,16.7 23.37,16.82 25.93,16.82
NETU7_1 on TOP (solid shape): 5.46,19.05 5.46,17.27 5.33,17.14 3.56,17.14 3.43,17.27 3.43,19.05 3.56,19.18 5.33,19.18
VA+5V on TOP (solid shape): 51.56,39.75 51.56,36.7 51.44,36.58 50.16,36.58 50.04,36.7 50.04,37.47 49.91,37.59 49.66,37.59 49.53,37.72 49.53,39.75 49.66,39.88 51.44,39.88
VA+5V on TOP (solid shape): 4.45,10.16 5.24,10.16 5.75,10.67 7.11,10.67 7.24,10.54 7.24,9.91 7.11,9.78 5.71,9.78 5.33,9.4 5.33,9.02 5.08,8.76 3.17,8.76 3.05,8.64 3.05,7.87 2.92,7.75 1.91,7.75 1.65,8 1.65,10.54 1.78,10.67 3.94,10.67
VA+5V on TOP (solid shape): 5.66,5.59 5.73,5.57 5.8,5.56 6.25,5.56 6.27,5.55 7.28,5.55 7.37,5.46 7.37,4.6 7.34,4.57 5.68,4.57 5.56,4.45 5.46,4.45 5.33,4.32 5.33,3.56 5.21,3.43 2.54,3.43 2.29,3.68 2.29,4.79 2.58,5.08 4.32,5.08 4.83,5.59
VA+5V on GND03: 1.46,4.95 1.46,27.86 1.98,28.38 7.43,28.38 7.43,25.96 8.18,25.21 14.05,25.21 17.34,28.5 17.34,29.77 25.48,37.91 39.2,37.91 39.22,37.93 41.61,37.93 42.74,39.05 42.74,43.26 41.35,44.64 25.97,44.64 24.64,43.31 24.64,40.26 22.48,38.1 20.19,38.1 19.25,39.04 19.25,40.97 20.95,42.67 20.95,45.59 21.84,46.48 51.69,46.48 51.69,36.99 51.28,36.58 50.01,36.58 49.15,35.72 49.15,35.08 48.74,34.67 34.13,34.67 33.31,33.85 25.32,33.85 22.03,30.56 22.03,14.05 21.51,13.53 15.16,13.53 5.83,4.19 2.22,4.19
VD+5V on TOP (solid shape): 51.56,35.69 51.56,32.64 51.44,32.51 50.16,32.51 50.04,32.64 50.04,35.69 50.16,35.81 51.44,35.81

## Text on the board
BOTTOM: ARTWORK BOTTOM
Board Geometry/Soldermask Bottom: SOLDERMASK BOTTOM
Package Geometry/Pastemask Bottom: PASTEMASK BOTTOM
Ref Des/Silkscreen Bottom: 230711 | 13kW_HVAC_Control_P2 | J5 | SILKSCREEN BOTTOM
TOP: ARTWORK TOP
Board Geometry/Soldermask Top: SOLDERMASK TOP
Package Geometry/Pastemask Top: PASTEMASK TOP
Ref Des/Silkscreen Top: A | B | C | SILKSCREEN TOP
GND02: GROUND PLANE02
GND03: GROUND PLANE03
ASSEMBLY_TOP: PRIMARY SIDE
ASSEMBLY_BOTTOM: SECONDARY SIDE
User.6: POWER PLANE02
User.18: FIGURE | SIZE | 10.0 | 40.0 | DRILL CHART: TOP to BOTTOM | ALL UNITS ARE IN MILS | PLATED | QTY | 408 | 40 | 59
